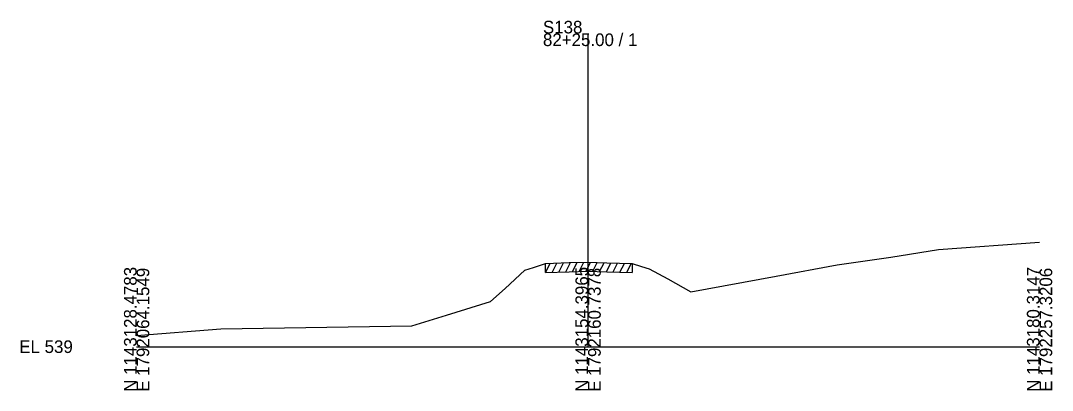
# Model space of a CAD drawing. Extents: x -26 to 1203, y -10 to 19606.
# Drawn here: x -25.7 to 202.8, y 4490.3 to 4572.3 of the extents above; entities that cross this region are included whole.
import ezdxf

# ---------------------------------------------------------------- set-up
doc = ezdxf.new("R2010")
doc.units = 0
for name, color, linetype in [('RD_EX_Driveway', 7, 'Continuous'), ('RD_GPK_XS_Cell', 7, 'Continuous'), ('RD_XS_ExGround', 7, 'Continuous'), ('RD_XS_ExPaveRet', 7, 'Continuous')]:
    doc.layers.add(name, color=color, linetype=linetype)

msp = doc.modelspace()

# ---------------------------------------------------------------- linework, layer by layer
at = {"layer": 'RD_GPK_XS_Cell'}
for p, q in [((100, 4500), (100, 4569.46)), ((0, 4500), (100, 4500)), ((100, 4500), (200, 4500))]:
    msp.add_line(p, q, dxfattribs=at)
at = {"layer": 'RD_XS_ExGround'}
msp.add_lwpolyline([(0, 4502.45), (18.66, 4503.95), (60.96, 4504.64), (68.64, 4507), (78.4, 4510), (81.64, 4512.91), (86, 4516.99), (87.9, 4517.56), (90.55, 4518.43), (95.84, 4518.63), (99.87, 4518.75), (104.18, 4518.6), (109.8, 4518.43), (111.82, 4517.8), (113.53, 4517.25), (117.63, 4515.08), (122.79, 4512.17), (141.68, 4515.65), (155.16, 4518.14), (167.04, 4519.82), (177.63, 4521.57), (200, 4523.15)], dxfattribs=at)
at = {"layer": 'RD_XS_ExPaveRet'}
for p, q in [((90.55, 4516.43), (91.57, 4518.47)), ((90.55, 4516.43), (90.55, 4518.43)), ((92.05, 4516.48), (93.07, 4518.52)), ((93.55, 4516.54), (94.57, 4518.58)), ((95.05, 4516.6), (96.07, 4518.63)), ((96.55, 4516.65), (97.57, 4518.68)), ((98.05, 4516.69), (99.07, 4518.72)), ((99.55, 4516.74), (100.54, 4518.72)), ((101.05, 4516.71), (102.03, 4518.67)), ((102.55, 4516.66), (103.53, 4518.62)), ((104.05, 4516.61), (105.03, 4518.58)), ((105.55, 4516.56), (106.53, 4518.53)), ((107.05, 4516.51), (108.03, 4518.48)), ((108.55, 4516.47), (109.53, 4518.44)), ((109.8, 4518.43), (109.8, 4516.43)), ((90.55, 4516.43), (95.84, 4516.63)), ((95.84, 4516.63), (99.87, 4516.75)), ((99.87, 4516.75), (104.18, 4516.6)), ((104.18, 4516.6), (109.8, 4516.43))]:
    msp.add_line(p, q, dxfattribs=at)

# ---------------------------------------------------------------- texts
at = {"layer": 'RD_EX_Driveway'}
msp.add_text('548.37', height=0.0975, rotation=90, dxfattribs=at).set_placement((100.1, 4518.74))
at = {"layer": 'RD_GPK_XS_Cell'}
for s, p in [('S138', (90, 4569.46)), ('82+25.00 / 1', (90, 4566.66)), ('EL 539', (-26, 4498.6))]:
    msp.add_text(s, height=2.8, dxfattribs=at).set_placement(p)
for s, p in [('N 1143128.4783', (0, 4490)), ('E 1792064.1549', (2.8, 4490)), ('N 1143154.3965', (100, 4490)), ('E 1792160.7378', (102.8, 4490)), ('N 1143180.3147', (200, 4490)), ('E 1792257.3206', (202.8, 4490))]:
    msp.add_text(s, height=2.8, rotation=90, dxfattribs=at).set_placement(p)

doc.saveas('drawing.dxf')
